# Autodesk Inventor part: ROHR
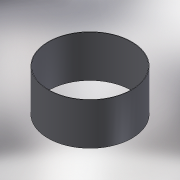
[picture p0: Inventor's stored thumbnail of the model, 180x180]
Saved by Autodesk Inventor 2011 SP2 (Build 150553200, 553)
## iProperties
Created: 2012-02
Part Number: ROHR
Material: S235JRG2
Document SubType Name: Modeling
Designer: SCHALLA
Density: 7.85 g/cm^3
Mass: 338356 g
Surface Area: 44334.2 cm^2
Volume: 43102.7 cm^3
MatBom2.0.1.: PS!Inventor!PV!15.0  SP: 1!AVMa!2!AVMi!0!AVBu!0
Author: SCHALLA
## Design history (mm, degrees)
derived "behaelter_multi_body.ipt"
node "Volumenkörper2"
feature "ROHR::behaelter_multi_body.ipt" dims "d2" = 10
tag "Bezeichnung1"
